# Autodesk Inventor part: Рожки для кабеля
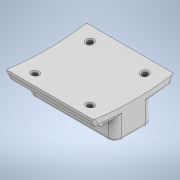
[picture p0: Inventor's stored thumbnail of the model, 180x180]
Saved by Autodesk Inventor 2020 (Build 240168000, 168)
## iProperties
Created: 2024-03
Part Number: Рожки для кабеля
Material: Типовые
Document SubType Name: Modeling
Designer: Pavel
Density: 1 g/cm^3
Appearance: По умолчанию
Author: Pavel
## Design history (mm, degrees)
sketch "Эскиз1"
  geometry: L1 (-24, 10)-(-24, -10); L2 (-16, 10)-(-16, -10); L3 (-16, -10)-(-16, -14); L4 (-24, -10)-(-24, -14); L5 (-16, -14)-(-16, -10); L6 (-16, 10)-(-16, 14); L7 (-24, 14)-(-24, 10); L8 (-16, 10)-(-16, 14); L9 (0, 30)-(-2, 30); L10 (0, -30)-(-2, -30); L11 (-2, 30)-(-6.301, 28); L12 (-2, -30)-(-6.301, -28); L13 (-24, 14)-(-7.818, 14); L14 (-24, -14)-(-7.818, -14); A1 r 195 centre (192.678, 0) between (0, 30) and (0, -30); A2 r 195 centre (186.678, 0) between (-6.58, 26) and (-6.58, -26); A3 r 195 centre (186.678, 0) between (-6.58, -26) and (-6.301, -28); A4 r 195 centre (186.678, 0) between (-6.301, 28) and (-6.58, 26); 4 further points
  constraints: 28 end point, 14 point on circle, 4 centre point, 4 parallel, 2 point on line, 1 horizontal, 1 perpendicular
  dimensions: "d0" = 195 radius of A1; "d3" = 195 radius of A2
extrude "Выдавливание1" new body sketch "Эскиз1" distance "d4" = 65; taper "d5" = 0 deg
sketch "Эскиз3"
  geometry: L1 (14, -24)-(-14, -24) reference; L2 (14, -7.818)-(14, -24) reference; L3 (-14, -24)-(14, -24); L4 (14, -24)-(14, -16); L5 (14, -16)-(-14, -16); L6 (-14, -16)-(-14, -24); L7 (-14, -24)-(-14, -7.818) reference; L8 (-14, -16)-(-14, -7.818); L9 (14, -7.818)-(14, -16); A1 r 195 centre (0, 186.678) between (-28, -6.301) and (-14, -7.818) reference; A2 r 195 centre (0, 186.678) between (-14, -7.818) and (14, -7.818); 1 further point
  constraints: 12 end point, 2 parallel, 2 point on circle, 1 centre point, 1 collinear, 1 horizontal, 1 perpendicular, 1 point on line, 1 vertical
  dimensions: "d9" = 195 radius of A2
extrude "Выдавливание3" cut sketch "Эскиз3" distance "d10" = 55; taper "d11" = 0 deg
node "РабПлоскость1"
sketch "Эскиз4"
  geometry: L1 (0, 65)-(0, 0) reference; L2 (0, 65)-(7, 65); L3 (7, 65)-(7, 53); L4 (7, 53)-(0, 53); L5 (0, 53)-(0, 65); L6 (0, 0)-(14.082, 0) reference; L7 (0, 0)-(7, 0); L8 (7, 0)-(7, 12); L9 (7, 12)-(0, 12); L10 (0, 12)-(0, 0); C1 r 2 at (7, 53); C2 r 2 at (7, 12); 1 further point
  constraints: 16 end point, 4 parallel, 2 centre point, 2 coincident, 2 horizontal, 2 perpendicular
  dimensions: "d12" = 7 distance of L3.end L4.end; "d13" = 12 distance of L2.end L3.end; "d14" = 7 distance of L9.end L8.end; "d15" = 12 distance of L8.end L7.end; "d16" = 4 diameter of C1; "d17" = 4 diameter of C2
extrude "Выдавливание4" cut sketch "Эскиз4" distance "d18" = 55; taper "d20" = 0 deg; dims "d19" = 27.5, "d21" = 0
sketch "Эскиз5"
  geometry: C1 r 5.5 at (7, 53); C2 r 5.5 at (7, 12); 1 further point
  constraints: 2 centre point
  dimensions: "d22" = 11 diameter of C1; "d23" = 11 diameter of C2
extrude "Выдавливание5" cut sketch "Эскиз5" distance "d24" = 2; taper "d25" = 0 deg; dims "d26" = 20, "d27" = 0
node "РабПлоскость2"
sketch "Эскиз6"
  geometry: L1 (0, 0)-(0, 65) reference; L2 (0, 0)-(7, 0); L3 (7, 0)-(7, 12); L4 (7, 12)-(0, 12); L5 (0, 12)-(0, 0); L6 (14.082, 65)-(0, 65) reference; L7 (0, 65)-(7, 65); L8 (7, 65)-(7, 53); L9 (7, 53)-(0, 53); L10 (0, 53)-(0, 65); C1 r 2 at (7, 53); C2 r 2 at (7, 12); 1 further point
  constraints: 16 end point, 4 parallel, 2 centre point, 2 coincident, 2 horizontal, 2 perpendicular
  dimensions: "d28" = 7 distance of L4.end L3.end; "d29" = 12 distance of L3.end L2.end; "d30" = 7 distance of L8.end L9.end; "d31" = 12 distance of L7.end L8.end; "d32" = 4 diameter of C1; "d33" = 4 diameter of C2
extrude "Выдавливание6" cut sketch "Эскиз6" distance "d34" = 20; taper "d36" = 0 deg; dims "d35" = 20, "d37" = 0
sketch "Эскиз7"
  geometry: C1 r 5.5 at (7, 12); C2 r 5.5 at (7, 53); 1 further point
  constraints: 2 centre point
  dimensions: "d38" = 11 diameter of C1; "d39" = 11 diameter of C2
extrude "Выдавливание7" cut sketch "Эскиз7" distance "d40" = 2; taper "d42" = 0 deg; dims "d41" = 1, "d43" = 0
sketch "Эскиз8"
  geometry: L1 (0, 28)-(0, 0) reference; L2 (65, 28)-(65, 0) reference; L3 (5, 0)-(60, 0); L4 (65, 5)-(65, 23); L5 (60, 28)-(5, 28); L6 (0, 23)-(0, 5); L7 (65, -14)-(65, 0) reference; L8 (0, 28)-(65, 28) reference; L9 (65, 0)-(0, 0); L10 (0, 0)-(0, 28); L11 (0, 28)-(65, 28); L12 (65, 28)-(65, 0); A1 r 5 centre (5, 23) between (5, 28) and (0, 23); A2 r 5 centre (5, 5) between (0, 5) and (5, 0); A3 r 5 centre (60, 5) between (60, 0) and (65, 5); A4 r 5 centre (60, 23) between (65, 23) and (60, 28); 8 further points
  constraints: 16 end point, 8 point on circle, 8 tangent, 4 centre point, 4 parallel, 4 point on line, 3 equal radius, 2 perpendicular, 1 horizontal
  dimensions: "d44" = 5 radius of A1 (derived)
extrude "Выдавливание8" cut sketch "Эскиз8" stored distance "d45" = 2; taper "d46" = 0 deg
fillet "Сопряжение1" dims "d47" = 2
fillet "Сопряжение2" dims "d48" = 1
node "Твердое тело1"
